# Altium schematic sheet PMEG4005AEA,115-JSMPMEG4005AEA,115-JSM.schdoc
size 127 x 101 mm
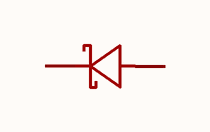
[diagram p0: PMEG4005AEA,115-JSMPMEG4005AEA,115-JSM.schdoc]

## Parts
D?  pmeg4005aea,115-jsm  [SOD-323_L1.6-W1.3-LS2.7-RD]  (value not drawn)

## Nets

Not connected (* = marked no-connect by the designer): D? 1(C) 2(A)

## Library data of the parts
D? = pmeg4005aea,115-jsm: 二极管配置:1个独立式;正向压降(Vf):510mV@500mA；620mV@1A;直流反向耐压(Vr):40V;整流电流:500mA;; Manufacturer: JSMSEMI(杰盛微); AddInBom: yes; ModelId: 39bca86493a8419684ee2090e9340edf; ModelTransform: 104.3305,51.181,0,0,0,0,0,0,0; Diode Configuration: 1个独立式; Voltage - DC Reverse(Vr): 40V; Current - Rectified: 500mA; Reverse Leakage Current (Ir): 10uA; Operating Junction Temperature Range: -55℃~+125℃; Non-Repetitive Peak Forward Surge Current: 22A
